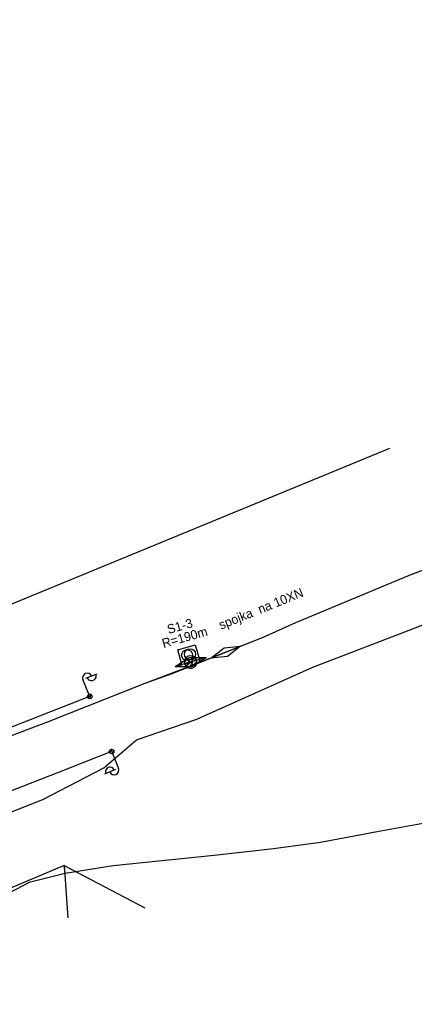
# Model space of a CAD drawing. Extents: x -748507 to -687366, y -1057342 to -1024924.
# Drawn here: x -745512.4 to -745426.2, y -1033619.4 to -1033402.7 of the extents above; entities that cross this region are included whole.
import ezdxf

# ---------------------------------------------------------------- set-up
doc = ezdxf.new("R2010")
doc.units = 0
for name, color, linetype in [('DK + TKK - SŽDC', 7, 'Continuous'), ('DK - Pha Holešovice - Kralupy - ČD TELEMATIKA', 7, 'Continuous'), ('Telefonica O2', 7, 'Continuous'), ('TK+DOK_Pha Holešovice - Kralupy', 7, 'Continuous'), ('Vedení NN - SŽDC', 7, 'Continuous')]:
    doc.layers.add(name, color=color, linetype=linetype)

msp = doc.modelspace()

# ---------------------------------------------------------------- linework, layer by layer
at = {"layer": 'DK + TKK - SŽDC'}
msp.add_lwpolyline([(-745400.08, -1033513.57), (-745427.68, -1033524.27), (-745452.16, -1033534.47), (-745459.47, -1033537.75), (-745479.21, -1033545.61), (-745485.05, -1033547.78), (-745506.18, -1033556.13), (-745534.69, -1033566.93), (-745565.92, -1033577.52), (-745596.01, -1033586.03), (-745626.14, -1033593.03), (-745643.48, -1033596.47), (-745650.81, -1033597.4), (-745661.52, -1033598.96), (-745666.31, -1033599.86), (-745684.01, -1033601.91)], dxfattribs=at)
at = {"layer": 'DK - Pha Holešovice - Kralupy - ČD TELEMATIKA'}
msp.add_lwpolyline([(-745431.67, -1033496.38), (-745534.27, -1033538.65), (-745554.49, -1033536.11), (-745662.86, -1033580.81)], dxfattribs=at)
at = {"layer": 'Telefonica O2'}
for points in [[(-745399.73, -1033572.96), (-745405.38, -1033574.87), (-745411.07, -1033576.35), (-745415.07, -1033576.69), (-745434.32, -1033580.2), (-745446.69, -1033582.52), (-745456.95, -1033583.91), (-745469.94, -1033585.35), (-745492.02, -1033587.61), (-745502.47, -1033589.3)], [(-745502.71, -1033587.52), (-745540.19, -1033603.31), (-745534.5, -1033615.11)], [(-745502.71, -1033587.52), (-745501.88, -1033598.94)], [(-745502.71, -1033587.52), (-745485.06, -1033596.78)], [(-745502.47, -1033589.3), (-745502.71, -1033587.52)], [(-745502.47, -1033589.3), (-745510.36, -1033591.27), (-745517.8, -1033595.11), (-745523.48, -1033598.16), (-745535.58, -1033603.24), (-745541.48, -1033605.02), (-745546.63, -1033606.1), (-745559.37, -1033609.12), (-745568.66, -1033611.24), (-745582.99, -1033614.39), (-745595.54, -1033616.77), (-745607.15, -1033618.64), (-745618.22, -1033619.09), (-745619.45, -1033619.36)]]:
    msp.add_lwpolyline(points, dxfattribs=at)
at = {"layer": 'TK+DOK_Pha Holešovice - Kralupy'}
for p, q in [((-745475.93, -1033540.36), (-745475.88, -1033540.36)), ((-745476.44, -1033543.06), (-745475.76, -1033542.38)), ((-745474.86, -1033543.28), (-745473.94, -1033542.36)), ((-745474.14, -1033542.1), (-745474.14, -1033542.1)), ((-745474.14, -1033542.1), (-745474.14, -1033542.1)), ((-745473.32, -1033543.12), (-745472.95, -1033542.45)), ((-745472.04, -1033542.31), (-745471.97, -1033542.17)), ((-745478.17, -1033544.01), (-745478.09, -1033543.91)), ((-745477.33, -1033544.04), (-745477.11, -1033543.63)), ((-745476.27, -1033543.7), (-745475.36, -1033542.79)), ((-745476.05, -1033544.01), (-745476.05, -1033544.01)), ((-745476.05, -1033544.01), (-745476.05, -1033544.01)), ((-745476.01, -1033544.04), (-745475.54, -1033543.19)), ((-745475.15, -1033544.02), (-745474.52, -1033542.9)), ((-745474.45, -1033543.68), (-745473.74, -1033542.97)), ((-745474.13, -1033544.01), (-745474.13, -1033544.01))]:
    msp.add_line(p, q, dxfattribs=at)
for points in [[(-745120.55, -1033402.72), (-745148.06, -1033411.76), (-745176.11, -1033422.32), (-745203.93, -1033433.49), (-745229.78, -1033443.94), (-745263.36, -1033457.66), (-745292.98, -1033469.66), (-745322.7, -1033481.81), (-745349.8, -1033492.68), (-745355.67, -1033495.12), (-745376.24, -1033503.59), (-745400.08, -1033513.57), (-745427.68, -1033524.27), (-745452.16, -1033534.47), (-745459.47, -1033537.75), (-745467.39, -1033540.91)], [(-745176.11, -1033422.32), (-745203.93, -1033433.49), (-745229.78, -1033443.94), (-745263.36, -1033457.66), (-745292.98, -1033469.66), (-745322.7, -1033481.81), (-745349.8, -1033492.68), (-745355.67, -1033495.12), (-745376.24, -1033503.59), (-745400.08, -1033513.57), (-745427.68, -1033524.27), (-745452.16, -1033534.47), (-745459.47, -1033537.75), (-745467.39, -1033540.91), (-745474.77, -1033543.84), (-745485.05, -1033547.78)], [(-745470.64, -1033542.22), (-745467.77, -1033539.98), (-745464.15, -1033539.59), (-745467.02, -1033541.83), (-745470.64, -1033542.22)], [(-745467.39, -1033540.91), (-745474.77, -1033543.84), (-745485.05, -1033547.78), (-745506.18, -1033556.13), (-745534.69, -1033566.93), (-745565.92, -1033577.52), (-745596.01, -1033586.03), (-745626.14, -1033593.03), (-745643.48, -1033596.47), (-745650.81, -1033597.4), (-745661.52, -1033598.96), (-745666.31, -1033599.86), (-745684.01, -1033601.91)], [(-745478.47, -1033544.02), (-745475.36, -1033542.08), (-745471.69, -1033542.09)], [(-745476.04, -1033542.1), (-745475.09, -1033543.06), (-745476.05, -1033544.01)], [(-745474.14, -1033542.1), (-745475.08, -1033543.06), (-745474.13, -1033544.01)], [(-745485.05, -1033547.78), (-745506.18, -1033556.13), (-745534.69, -1033566.93), (-745565.92, -1033577.52), (-745596.01, -1033586.03), (-745626.14, -1033593.03), (-745643.48, -1033596.47), (-745650.81, -1033597.4), (-745661.52, -1033598.96), (-745666.31, -1033599.86), (-745684.01, -1033601.91)]]:
    msp.add_lwpolyline(points, dxfattribs=at)
for points in [[(-745477.91, -1033540.41), (-745474.07, -1033539.32), (-745473.16, -1033542.51), (-745477, -1033543.6)], [(-745478.47, -1033544.02), (-745474.8, -1033544.04), (-745471.69, -1033542.09)]]:
    msp.add_lwpolyline(points, close=True, dxfattribs=at)
for centre in [(-745475.84, -1033541.56), (-745475.21, -1033541.35)]:
    msp.add_circle(centre, 1.2, dxfattribs=at)
for centre, start, end in [((-745475.09, -1033543.06), 134.534, 224.7711), ((-745475.08, -1033543.06), 45.4863, 134.8523), ((-745475.08, -1033543.06), 315.2492, 45.4863), ((-745475.09, -1033543.06), 224.7724, 315.5618)]:
    msp.add_arc(centre, 1.35, start, end, dxfattribs=at)
at = {"layer": 'Vedení NN - SŽDC'}
for p, q in [((-745497.3, -1033550.11), (-745498.6, -1033546.86)), ((-745497.95, -1033546.6), (-745495.53, -1033545.63)), ((-745497.5, -1033550.89), (-745497.15, -1033550.08)), ((-745497.17, -1033551.07), (-745496.79, -1033550.19)), ((-745492.28, -1033562.12), (-745492.66, -1033563)), ((-745491.95, -1033562.3), (-745492.29, -1033563.11)), ((-745492.15, -1033563.08), (-745490.84, -1033566.32)), ((-745491.49, -1033566.58), (-745493.9, -1033567.55))]:
    msp.add_line(p, q, dxfattribs=at)
for points in [[(-745631.39, -1033610.02), (-745631, -1033611.52), (-745629.52, -1033611.59), (-745626.19, -1033611.31), (-745609.27, -1033607.45), (-745595.55, -1033605.58), (-745565.58, -1033597.57), (-745541.45, -1033589.74), (-745530.27, -1033583.57), (-745515.64, -1033576.36), (-745507.34, -1033573.1), (-745494.01, -1033566.15), (-745486.92, -1033560.08), (-745473.73, -1033555.55), (-745448.37, -1033544.19), (-745425.45, -1033535.39), (-745418.84, -1033532.6), (-745415.14, -1033534.73), (-745407.96, -1033532.2), (-745405.1, -1033530.37), (-745395.48, -1033525.68), (-745387.25, -1033522.76), (-745371.53, -1033515.62)], [(-745497.15, -1033550.57), (-745510.14, -1033555.7), (-745519.3, -1033559.25), (-745528.1, -1033562.56), (-745542.47, -1033567.67), (-745556.38, -1033572.5), (-745561.06, -1033574.29), (-745570.54, -1033577.02), (-745577.36, -1033578.97), (-745578.17, -1033576.16), (-745577.44, -1033576.49)], [(-745580.64, -1033593.33), (-745569.66, -1033590.2), (-745557.01, -1033586.31), (-745552.77, -1033584.8), (-745539.64, -1033580.55), (-745523.65, -1033574.61), (-745514.74, -1033571.39), (-745504.07, -1033567.23), (-745492.3, -1033562.57)]]:
    msp.add_lwpolyline(points, dxfattribs=at)
for centre in [(-745497.11, -1033550.57), (-745497.11, -1033550.57), (-745492.34, -1033562.61), (-745492.34, -1033562.61)]:
    msp.add_circle(centre, 0.5, dxfattribs=at)
for centre, start, end in [((-745497.67, -1033546.49), 21.8149, 201.8149), ((-745496.74, -1033546.13), 201.1123, 22.5174), ((-745492.7, -1033567.06), 21.2372, 202.6423), ((-745491.77, -1033566.69), 201.9397, 21.9397)]:
    msp.add_arc(centre, 1, start, end, dxfattribs=at)

# ---------------------------------------------------------------- texts
at = {"layer": 'TK+DOK_Pha Holešovice - Kralupy'}
for s, rotation, p in [('spojka  na 10XN', 22.0037, (-745468.44, -1033536)), ('S1-3', 15.8495, (-745479.89, -1033536.95)), ('R=190m', 15.8495, (-745481, -1033540.01))]:
    msp.add_text(s, height=2, rotation=rotation, dxfattribs=at).set_placement(p)

doc.saveas('drawing.dxf')
